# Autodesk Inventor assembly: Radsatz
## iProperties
Created: 2003-04
Part Number: Radsatz
Document SubType Name: Baugruppe
Designer: Administrator
Control State: 0
Master: False
Checked Out: False
Shininess: 20.0
Angle Display Precision: 2
Document Length Units: 11269
Document Angle Units: 11279
Document Time Units: 11290
Document Mass Units: 11283
Document Length Units Precision: 3
Document Angle Units Precision: 2
Density: 0.0
Volumn: 0.0
Area: 0.0
PropertySet Name: Model Information
Author: Administrator
